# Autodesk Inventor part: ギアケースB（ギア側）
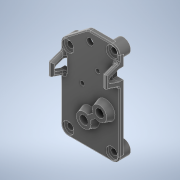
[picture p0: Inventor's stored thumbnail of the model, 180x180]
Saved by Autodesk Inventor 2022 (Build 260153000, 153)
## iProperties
Created: 2024-09
Part Number: ギアケースB（ギア側）
Material: ABS プラスチック
Document SubType Name: Modeling
Designer: shimizu
Density: 1.06 g/cm^3
Appearance: 滑らか - 白
Author: shimizu
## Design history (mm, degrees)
sketch "スケッチ1"
  geometry: L1 (0, 35.5)-(10.5, 35.5); L2 (14, 32)-(14, -10); L3 (10.5, -13.5)-(-10.5, -13.5); L4 (-14, -10)-(-14, 24); L5 (-2.121, 34.784)-(-12.621, 26.784); A1 r 3.5 centre (0, 32) between (0, 35.5) and (-2.121, 34.784); A2 r 3.5 centre (-10.5, 24) between (-12.621, 26.784) and (-14, 24); A3 r 3.5 centre (10.5, 32) between (14, 32) and (10.5, 35.5); A4 r 3.5 centre (10.5, -10) between (10.5, -13.5) and (14, -10); A5 r 3.5 centre (-10.5, -10) between (-14, -10) and (-10.5, -13.5); 1 further point
  constraints: 10 end point, 10 point on circle, 10 tangent, 5 centre point, 2 equal radius, 2 parallel, 1 horizontal, 1 perpendicular, 1 vertical alignment
  dimensions: "d0" = 13.5 distance from line of L3 point (0, 0); "d1" = 49 distance between parallel lines of L1 L3; "d2" = 28 distance between parallel lines of L2 L4; "d3" = 14 distance from line of L2 point (0, 0); "d4" = 7 diameter of A1; "d5" = 7 diameter of A2; "d6" = 24 vertical distance of point (0, 0) A2.centre; "d7" = 3.5 radius of A3
extrude "押し出し1" new body sketch "スケッチ1" distance "d8" = 2; taper "d9" = 0 deg
sketch "スケッチ2"
  geometry: C1 r 3.5 at (-10.5, 32); C2 r 3.5 at (10.5, 24); C3 r 3.5 at (-10.5, -10); C4 r 3.5 at (10.5, -10); A1 r 3.5 centre (-10.5, -10) between (-14, -10) and (-10.5, -13.5) reference; A2 r 3.5 centre (10.5, -10) between (10.5, -13.5) and (14, -10) reference; A3 r 3.5 centre (10.5, 24) between (14, 24) and (12.621, 26.784) reference; A4 r 3.5 centre (-10.5, 32) between (-10.5, 35.5) and (-14, 32) reference; 1 further point
  constraints: 8 concentric, 4 centre point
extrude "押し出し2" join sketch "スケッチ2" distance "d10" = 3.5; taper "d11" = 0 deg
sketch "スケッチ3"
  geometry: C1 r 3 at (0, 0); C2 r 3 at (21, -8); C3 r 3 at (0, -42); C4 r 3 at (21, -42); C5 r 3.5 at (0, 0) reference; C6 r 3.5 at (21, -8) reference; C7 r 3.5 at (0, -42) reference; C8 r 3.5 at (21, -42) reference; 1 further point
  constraints: 4 centre point, 4 concentric, 3 equal radius
  dimensions: "d12" = 6 diameter of C1
extrude "押し出し3" cut sketch "スケッチ3" distance "d13" = 0.5; taper "d14" = 0 deg
sketch "スケッチ4"
  geometry: C1 r 4.5 at (7.5, 6.5); C2 r 4.5 at (0, 0); 1 further point
  constraints: 2 centre point, 1 coincident
  dimensions: "d15" = 9 diameter of C2; "d16" = 9 diameter of C1; "d17" = 6.5 vertical distance of point (0, 0) C1.centre; "d18" = 7.5 horizontal distance of point (0, 0) C1.centre
extrude "押し出し4" join sketch "スケッチ4" distance "d19" = 3; taper "d20" = -18.4 deg
sketch "スケッチ5"
  geometry: L1 (7.5, 6.5)-(0, 0); L2 (6.845, 7.256)-(-0.655, 0.756); L3 (8.155, 5.744)-(0.655, -0.756); L4 (6.845, 7.256)-(8.155, 5.744); L5 (-0.655, 0.756)-(0.655, -0.756); C1 r 2.336 at (7.5, 6.5); C2 r 2.527 at (0, 0); C3 r 3.502 at (7.5, 6.5) reference; C4 r 3.502 at (0, 0) reference; 5 further points
  constraints: 10 end point, 5 parallel, 2 centre point, 2 coincident, 2 concentric, 1 midpoint, 1 perpendicular
  dimensions: "d21" = 1 distance between parallel lines of L1 L2; "d22" = 1 distance between parallel lines of L1 L3
extrude "押し出し5" join sketch "スケッチ5" stored distance "d23" = 3; taper "d24" = 0 deg
sketch "スケッチ6"
  geometry: C1 r 3 at (3.76, 11.92); 1 further point
  constraints: 1 centre point
  dimensions: "d25" = 6 diameter of C1; "d26" = 3.76 horizontal distance of point (0, 0) C1.centre; "d27" = 11.92 vertical distance of point (0, 0) C1.centre
extrude "押し出し6" join sketch "スケッチ6" distance "d28" = 4; taper "d29" = -7.1 deg
sketch "スケッチ7"
  geometry: L1 (-3.72, 20.65)-(6.28, 20.65); L2 (-3.72, 20.65)-(6.28, 20.65); L3 (-3.72, 20.65)-(-3.72, 10.65); L4 (-3.72, 20.65)-(6.28, 20.65); L5 (-3.72, 20.65)-(-3.72, 10.65); A1 r 10 centre (-3.72, 20.65) between (-3.72, 10.65) and (6.28, 20.65); 2 further points
  constraints: 10 end point, 3 collinear, 2 point on circle, 1 centre point, 1 horizontal
  dimensions: "d30" = 0 distance between parallel lines of L1 L2; "d31" = 90 deg angle of L3 L1; "d33" = 3.72 horizontal distance of point (0, 0) L1.start; "d34" = 20.65 vertical distance of point (0, 0) L1.start; "d35" = 10 radius of A1
extrude "押し出し7" cut sketch "スケッチ7" extent not by distance; stored distance "d36" = 0; taper "d37" = 0 deg
sketch "スケッチ8"
  geometry: C1 r 1.05 at (3.72, 20.65); C2 r 1.05 at (-3.76, 11.92); C3 r 1.6 at (0, 31); C4 r 1.5 at (-10.5, 24); C5 r 1.5 at (10.5, 32); C6 r 1.5 at (-10.5, -10); C7 r 1.5 at (10.5, -10); C8 r 3 at (-10.5, 24) reference; C9 r 3 at (10.5, 32) reference; C10 r 3 at (-10.5, -10) reference; C11 r 3 at (10.5, -10) reference; C12 r 2.05 at (7.5, 6.5); C13 r 2.05 at (0, 0); A1 r 10 centre (3.72, 20.65) between (-4.423, 14.846) and (-0.767, 11.713) reference; A2 r 2.502 centre (-3.76, 11.92) between (-4.087, 14.4) and (-1.259, 11.978) reference; A3 r 3.502 centre (7.5, 6.5) between (5.619, 3.546) and (4.309, 5.058) reference; A4 r 3.502 centre (0, 0) between (1.881, 2.954) and (3.191, 1.442) reference; 1 further point
  constraints: 9 centre point, 8 concentric, 3 equal radius, 1 vertical alignment
  dimensions: "d38" = 2.1 diameter of C1; "d39" = 2.1 diameter of C2; "d40" = 3.2 diameter of C3; "d41" = 31 distance of point (0, 0) C3.centre; "d42" = 3 diameter of C4; "d43" = 4.1 diameter of C12; "d44" = 4.1 diameter of C13
extrude "押し出し8" cut sketch "スケッチ8" extent not by distance; stored distance "d45" = 3; taper "d46" = 0 deg
sketch "スケッチ9"
  geometry: L1 (-8.764, 34.013)-(16.229, 34.013); L2 (-8, 37.013)-(-8, 31.013); L3 (-8, 37.013)-(-2, 39.013); L4 (-2, 0)-(-2, 42) reference; L5 (-8, 31.013)-(-2, 29.013); L6 (-2, 36.761)-(-5.974, 35.436); L7 (-2, 31.265)-(-5.974, 32.59); A1 r 1.5 centre (-5.5, 34.013) between (-5.974, 35.436) and (-5.974, 32.59); 1 further point
  constraints: 12 end point, 5 point on line, 2 parallel, 2 point on circle, 2 tangent, 1 centre point, 1 horizontal, 1 vertical
  dimensions: "d47" = 6 distance of L2.start L2.end; "d48" = 3 distance from line of L1 L2.start; "d49" = 5 distance from line of L1 L3.end; "d50" = 5 distance from line of L1 L5.end; "d51" = 6 distance between parallel lines of L4 L2; "d52" = 3 diameter of A1; "d53" = 3.5 distance from line of L4 A1.centre
extrude "押し出し9" join sketch "スケッチ9" distance "d54" = 2; taper "d55" = 0 deg
sketch "スケッチ10"
  geometry: L1 (-2, 36.761)-(-5.974, 35.436) reference; L2 (0, 0)-(0, 42) reference; L3 (-2, 36.761)-(0, 36.761); L4 (0, 36.761)-(0, 31.265); L5 (0, 31.265)-(-2, 31.265); L6 (-2, 31.265)-(-2, 36.761); L7 (-2, 31.265)-(-5.974, 32.59) reference; 2 further points
  constraints: 8 end point, 2 parallel, 2 point on line, 1 horizontal, 1 perpendicular
extrude "押し出し10" cut sketch "スケッチ10" distance "d56" = 3; taper "d57" = 0 deg
sketch "スケッチ11"
  geometry: L1 (-19.547, 26)-(25.335, 26); L2 (8, 29)-(8, 23); L3 (2, 34)-(2, 0) reference; L4 (8, 29)-(2, 31); L5 (8, 23)-(2, 21); L6 (2, 28.748)-(5.974, 27.423); L7 (5.974, 24.577)-(2, 23.252); L8 (2, 22.97)-(2, 20.87) reference; A1 r 1.5 centre (5.5, 26) between (5.974, 24.577) and (5.974, 27.423); 2 further points
  constraints: 12 end point, 5 point on line, 2 parallel, 2 point on circle, 2 tangent, 1 centre point, 1 horizontal, 1 vertical
  dimensions: "d58" = 16 distance from line of point (0, 10) L1; "d59" = 6 distance of L2.start L2.end; "d60" = 3 distance from line of L2.start L1; "d61" = 6 distance between parallel lines of L3 L2; "d62" = 5 distance from line of L1 L4.end; "d63" = 5 distance from line of L1 L5.end; "d64" = 3 diameter of A1; "d65" = 3.5 distance from line of L3 A1.centre
extrude "押し出し11" join sketch "スケッチ11" distance "d66" = 2; taper "d67" = 0 deg
sketch "スケッチ12"
  geometry: L1 (0, 34)-(0, 0) reference; L2 (2, 0)-(2, 29.013) reference; L3 (0, 28.748)-(2, 28.748); L4 (2, 28.748)-(2, 23.252); L5 (2, 23.252)-(0, 23.252); L6 (0, 23.252)-(0, 28.748); 2 further points
  constraints: 8 end point, 2 parallel, 1 horizontal, 1 perpendicular, 1 point on line
extrude "押し出し12" cut sketch "スケッチ12" distance "d68" = 3; taper "d69" = 0 deg
fillet "フィレット1" dims "d70" = 1
sketch "スケッチ13"
  geometry: C1 r 2.8 at (10.5, 32); C2 r 2.8 at (-10.5, 24); C3 r 2.8 at (10.5, -10); C4 r 2.8 at (-10.5, -10); C5 r 1.5 at (10.5, 32) reference; C6 r 1.5 at (-10.5, 24) reference; C7 r 1.5 at (10.5, -10) reference; C8 r 1.5 at (-10.5, -10) reference; 1 further point
  constraints: 4 centre point, 4 concentric, 3 equal radius
  dimensions: "d71" = 5.6 diameter of C1
extrude "押し出し13" cut sketch "スケッチ13" distance "d72" = 1; taper "d73" = 0 deg
fillet "フィレット2" dims "d74" = 0.5
node "ソリッド1"
